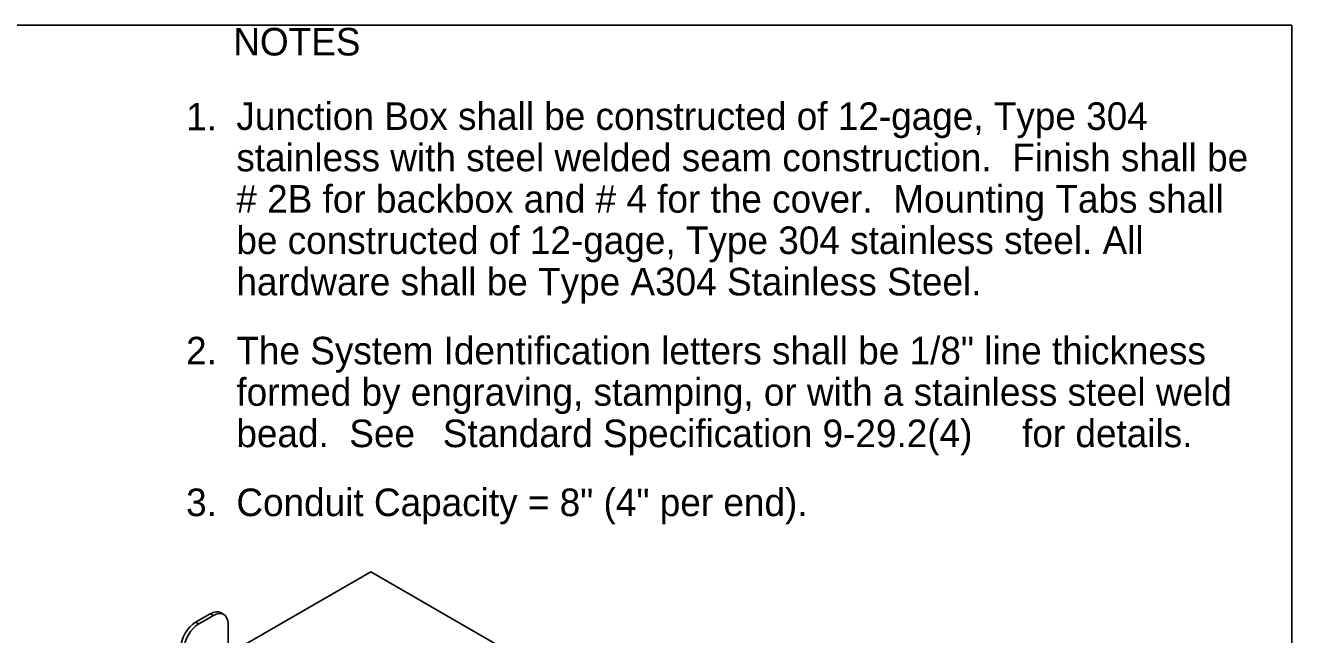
# Model space of a CAD drawing. Extents: x 99862 to 103151, y 100000 to 105076.
# Drawn here: x 102234 to 103151, y 101634 to 102076 of the extents above; entities that cross this region are included whole.
import ezdxf

# ---------------------------------------------------------------- set-up
doc = ezdxf.new("R2010")
doc.units = 0
for name, color, linetype in [('Level 1', 7, 'Continuous'), ('Level 2', 7, 'Continuous'), ('Level 20', 7, 'Continuous'), ('Level 3', 7, 'Continuous'), ('Level 60', 7, 'Continuous')]:
    doc.layers.add(name, color=color, linetype=linetype)

msp = doc.modelspace()

# ---------------------------------------------------------------- linework, layer by layer
at = {"layer": 'Level 1'}
msp.add_lwpolyline([(99862, 99999.5), (103151, 99999.5), (103151, 102075.5), (99862, 102075.5)], close=True, dxfattribs=at)
at = {"layer": 'Level 2'}
for p, q in [((102484.03, 101679.29), (102380.61, 101619.58)), ((102870.34, 101456.25), (102484.03, 101679.29))]:
    msp.add_line(p, q, dxfattribs=at)
at = {"layer": 'Level 3'}
for p, q in [((102367.77, 101648.91), (102357.16, 101642.78)), ((102370.01, 101647.62), (102359.4, 101641.49)), ((102367.77, 101648.91), (102370.01, 101647.62)), ((102377.51, 101648.36), (102375.27, 101649.65)), ((102359.4, 101641.49), (102357.16, 101642.78)), ((102380.61, 101641.49), (102380.61, 101619.58))]:
    msp.add_line(p, q, dxfattribs=at)
for centre, major_axis, start_param, end_param in [((102367.77, 101636.66), (7.5, 12.99), 6.283185, 7.068583), ((102370.01, 101635.37), (-7.5, -12.99), 3.141593, 3.926991), ((102370.01, 101635.37), (-7.5, -12.99), 2.356194, 3.141593), ((102357.16, 101630.54), (7.5, 12.99), 0.785398, 2.356194), ((102359.4, 101629.24), (-7.5, -12.99), 3.926991, 5.497787)]:
    msp.add_ellipse(centre, major_axis=major_axis, ratio=0.57735, start_param=start_param, end_param=end_param, dxfattribs=at)
at = {"layer": 'Level 60'}
msp.add_line((103151, 102075.5), (103151, 102075.5), dxfattribs=at)

# ---------------------------------------------------------------- texts
at = {"layer": 'Level 20'}
for s, p in [('NOTES', (102384.42, 102053.62)), ('Junction Box shall be constructed of 12-gage, Type 304 ', (102386.66, 101999.64)), ('1.', (102350.26, 101999.24)), ('stainless with steel welded seam construction.  Finish shall be ', (102386.66, 101969.64)), ('# 2B for backbox and # 4 for the cover.  Mounting Tabs shall', (102386.66, 101939.64)), ('be constructed of 12-gage, Type 304 stainless steel. All ', (102386.66, 101909.64)), ('hardware shall be Type A304 Stainless Steel.', (102386.66, 101879.64)), ('2.', (102350.26, 101829.64)), ('The System Identification letters shall be 1/8" line thickness ', (102386.66, 101829.64)), ('formed by engraving, stamping, or with a stainless steel weld ', (102386.66, 101799.64)), ('bead.  See ', (102386.66, 101769.64)), ('Standard Specification 9-29.2(4)', (102536.19, 101769.64)), (' for details.', (102948.32, 101769.64)), ('3.', (102350.26, 101719.64)), ('Conduit Capacity = 8" (4" per end).', (102386.66, 101719.64))]:
    msp.add_text(s, height=20, dxfattribs=at).set_placement(p)

doc.saveas('drawing.dxf')
